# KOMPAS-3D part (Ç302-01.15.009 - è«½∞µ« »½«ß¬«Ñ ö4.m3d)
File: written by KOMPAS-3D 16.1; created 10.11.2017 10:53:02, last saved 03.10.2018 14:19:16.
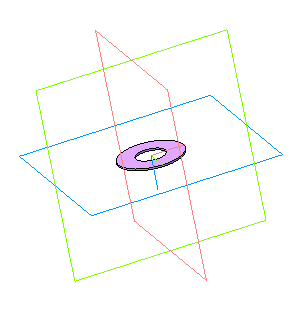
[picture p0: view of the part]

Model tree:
1. Эскиз:1
2. Операция выдавливания:1  (labels: Фторопласт-4  ГОСТ 10007-80 Е)
     Расстояние 1 = 0.5

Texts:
  Кольцо плоское Ф4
